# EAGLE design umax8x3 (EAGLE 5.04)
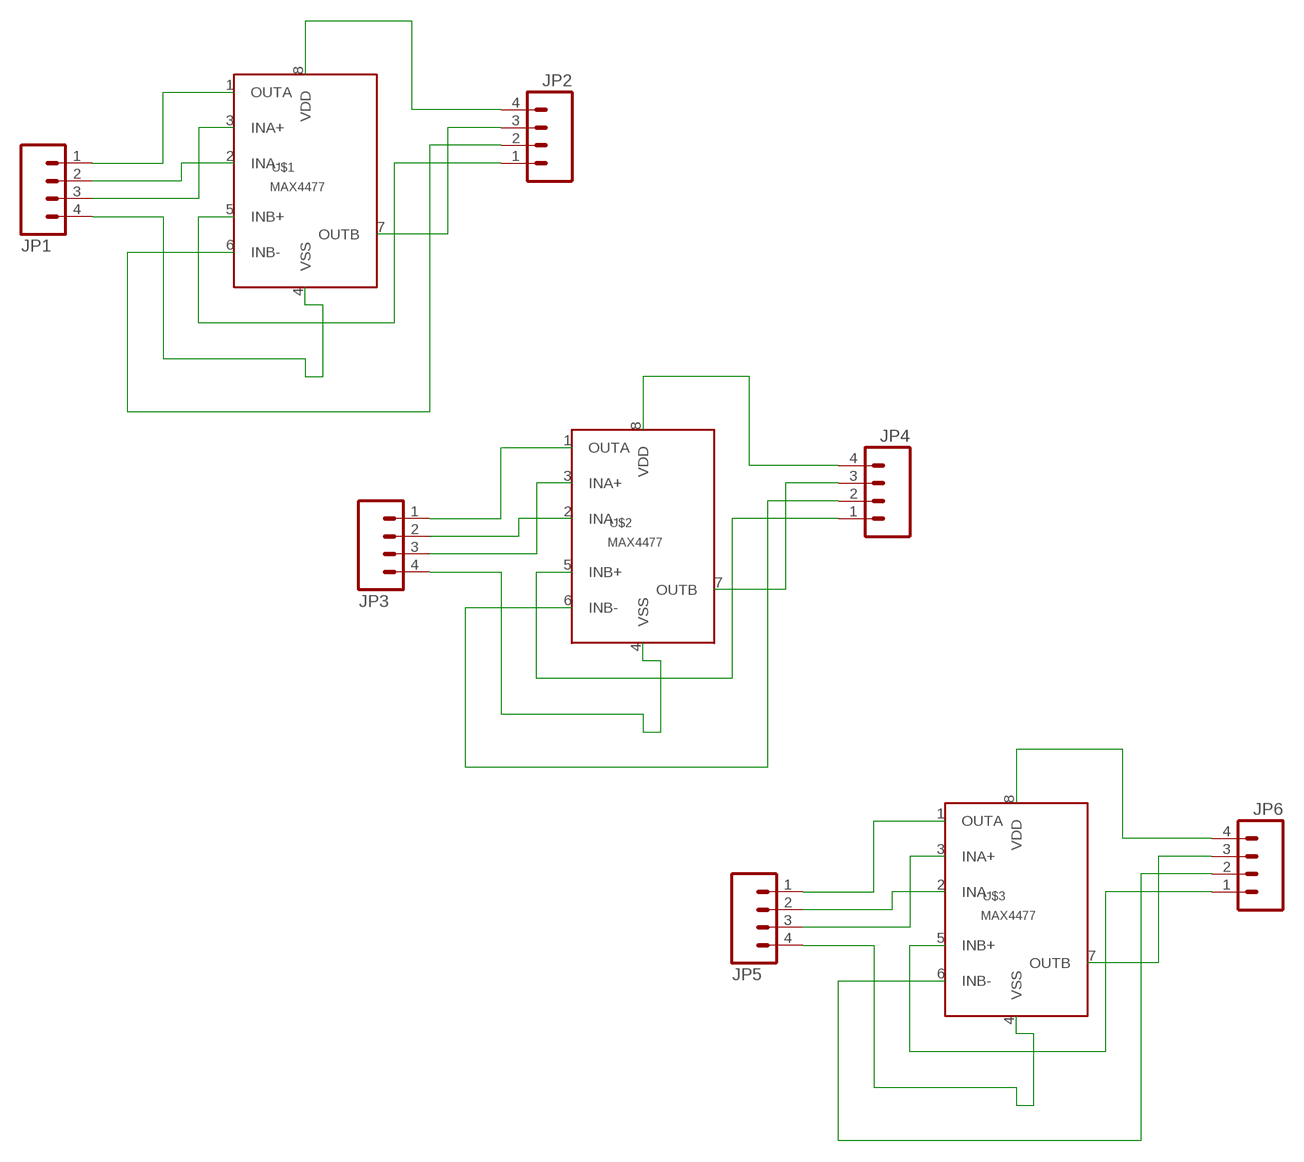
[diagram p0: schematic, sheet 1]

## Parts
JP1  M04PTH  [1X04]
JP2  M04PTH  [1X04]
JP3  M04PTH  [1X04]
JP4  M04PTH  [1X04]
JP5  M04PTH  [1X04]
JP6  M04PTH  [1X04]
U$1  MAX4477  [UMAX8]
U$2  MAX4477  [UMAX8]
U$3  MAX4477  [UMAX8]

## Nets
N$1: JP1.1 U$1.1(OUTA)
N$2: JP1.2 U$1.2(INA-)
N$3: JP1.3 U$1.3(INA+)
N$4: JP1.4 U$1.4(VSS)
N$5: JP2.1 U$1.5(INB+)
N$6: JP2.2 U$1.6(INB-)
N$7: JP2.3 U$1.7(OUTB)
N$8: JP2.4 U$1.8(VDD)
N$9: JP3.1 U$2.1(OUTA)
N$10: JP3.2 U$2.2(INA-)
N$11: JP3.3 U$2.3(INA+)
N$12: JP3.4 U$2.4(VSS)
N$13: JP4.1 U$2.5(INB+)
N$14: JP4.2 U$2.6(INB-)
N$15: JP4.3 U$2.7(OUTB)
N$16: JP4.4 U$2.8(VDD)
N$17: JP5.1 U$3.1(OUTA)
N$18: JP5.2 U$3.2(INA-)
N$19: JP5.3 U$3.3(INA+)
N$20: JP5.4 U$3.4(VSS)
N$21: JP6.1 U$3.5(INB+)
N$22: JP6.2 U$3.6(INB-)
N$23: JP6.3 U$3.7(OUTB)
N$24: JP6.4 U$3.8(VDD)

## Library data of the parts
JP1-JP6 = SparkFun:M04: Header 4 Standard 4-pin 0.1" header. Use with straight break away headers (SKU : PRT-00116), right angle break away headers (PRT-00553), swiss pins (PRT-00743), machine pins (PRT-00117), and female headers (PRT-00115). Molex polarized connector foot print use with SKU : PRT-08231 with associated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
U$1-U$3 = trl:MAX4477

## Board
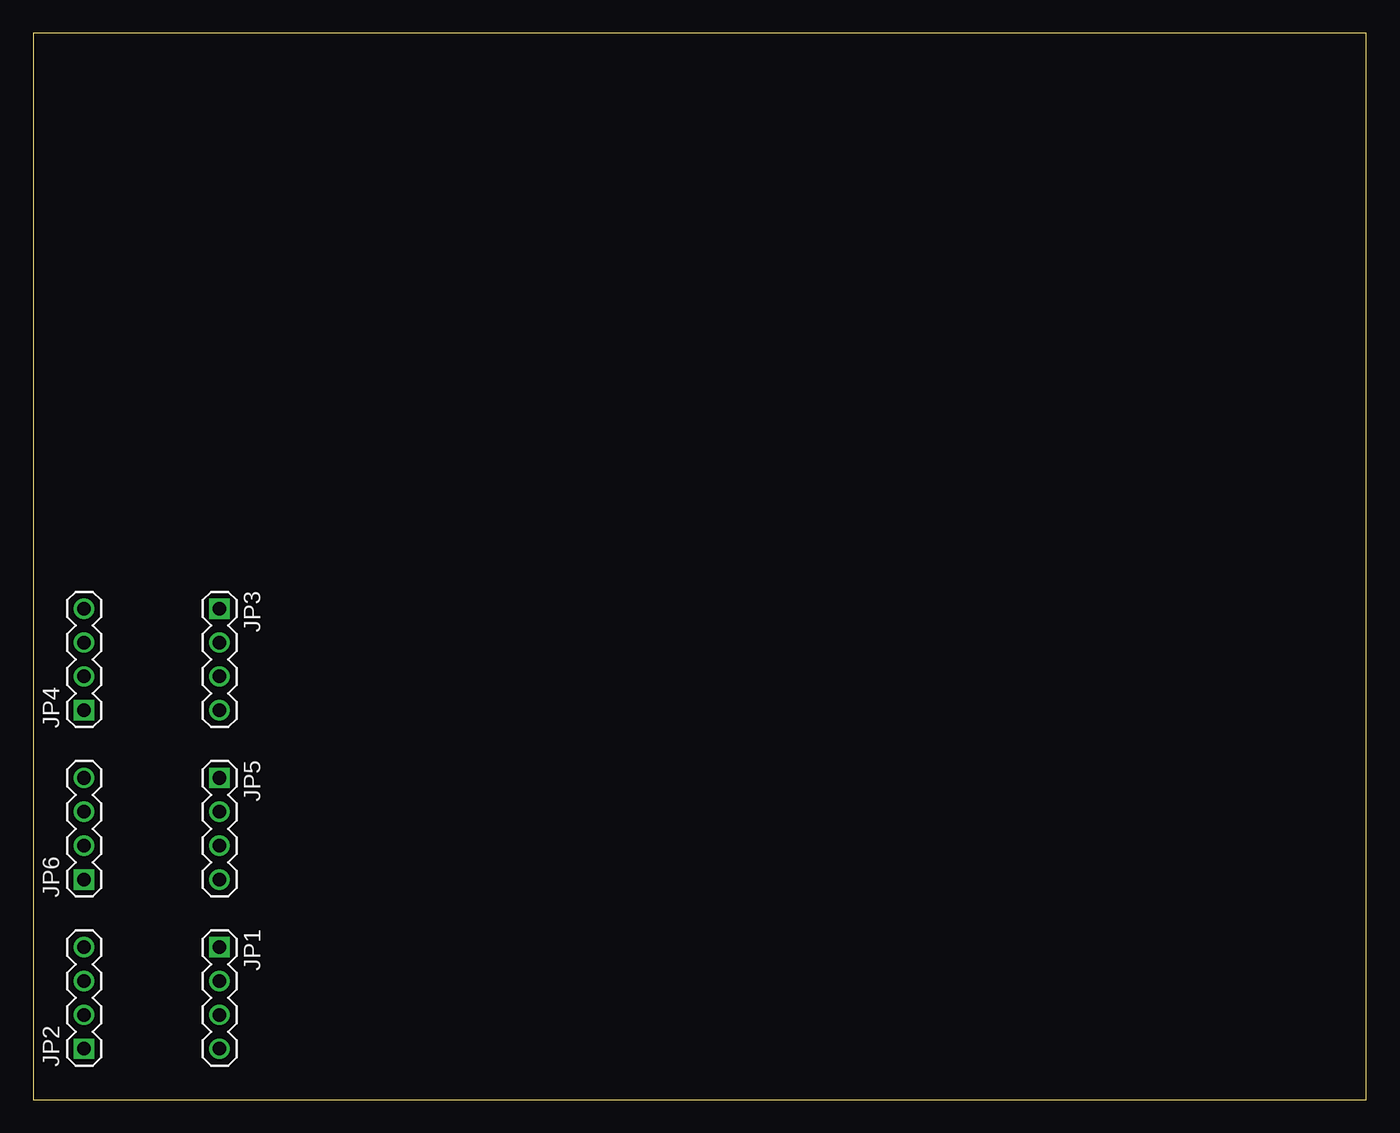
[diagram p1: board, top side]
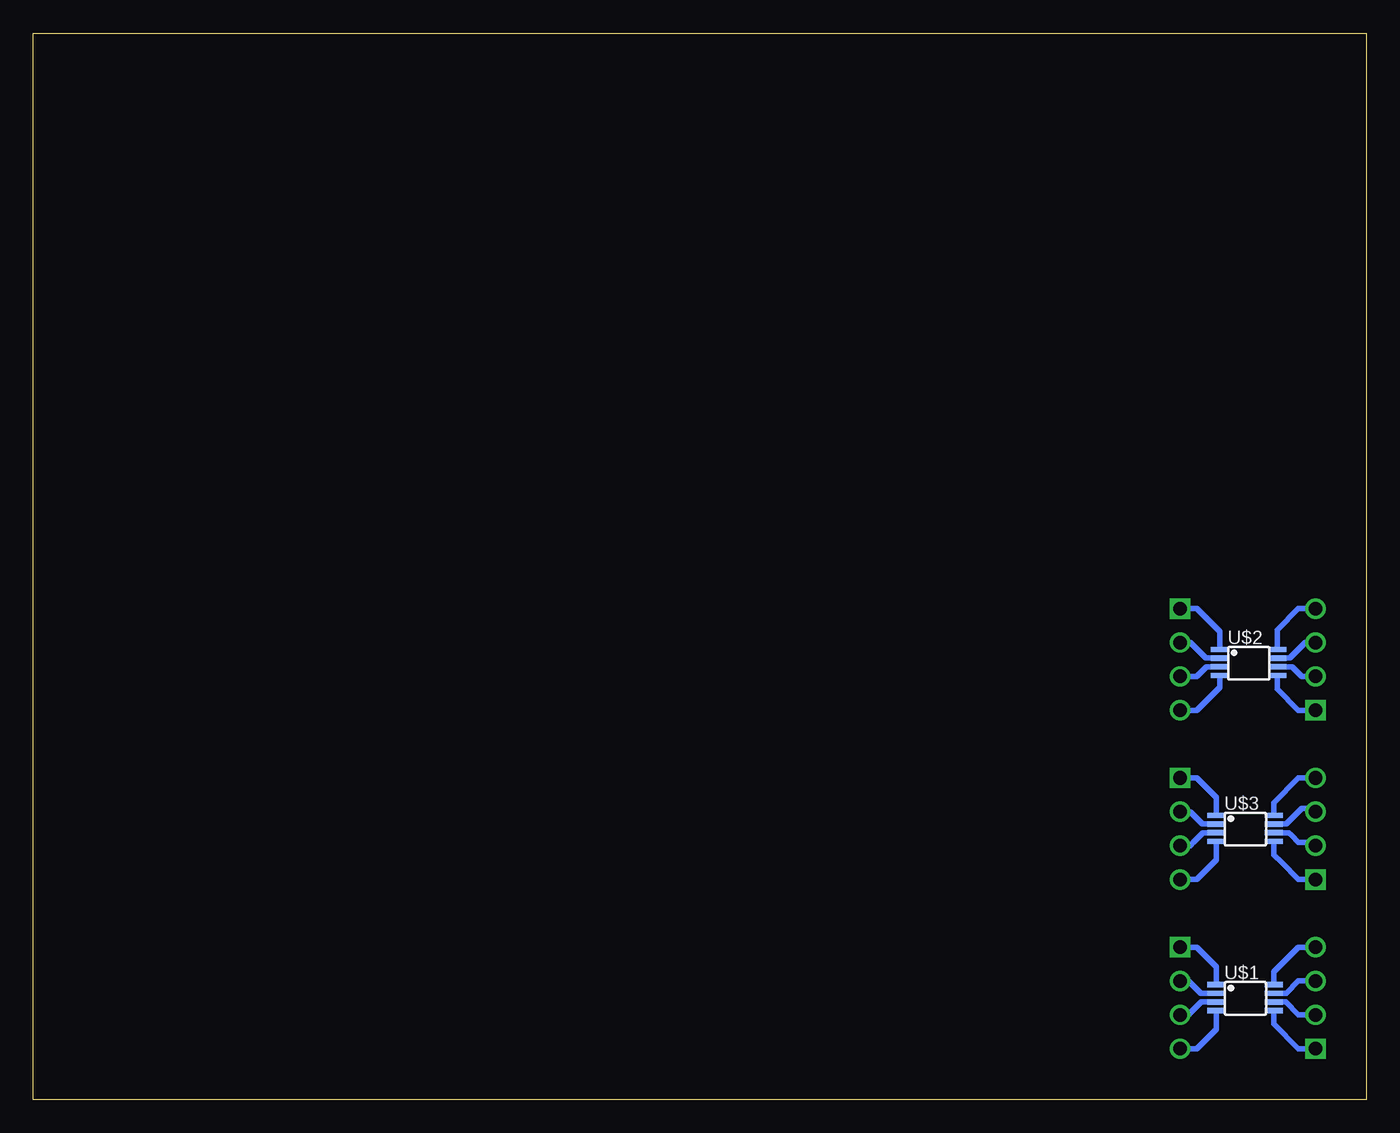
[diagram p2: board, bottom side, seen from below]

Size 100 x 80 mm. Coordinates in mm from the lower left corner, seen from the top.
Outline: 0,0 100,0 100,80 0,80 0,0
Copper layers (1*16): Top 0.035mm / dielectric 1.5mm / Bottom 0.035mm
Design rules "default": minimum track width 10mil, minimum drill 24mil, track to track 8mil, track to pad 8mil, pad to pad 8mil, via to via 8mil, smd to smd 8mil, copper to edge 40mil, drill to drill 8mil, minimum pad ring 10mil, minimum via ring 8mil, stop-mask expansion 4mil, vias tented up to drill 0mil, thermal gap 10mil

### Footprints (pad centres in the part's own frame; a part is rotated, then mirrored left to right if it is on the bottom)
1X04 = drill 1.016 square: 1 0,0 | drill 1.016 round: 2 2.54,0; 3 5.08,0; 4 7.62,0
UMAX8 = smd 1.35 x 0.4: 1 -2.35,1; 2 -2.35,0.35; 3 -2.35,-0.3; 4 -2.35,-0.95; 5 1.95,-0.95; 6 1.95,-0.3; 7 1.95,0.35; 8 1.95,1

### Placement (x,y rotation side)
JP1  13.97,11.43 270 top
JP2  3.81,3.81 90 top
JP3  13.97,36.83 270 top
JP4  3.81,29.21 90 top
JP5  13.97,24.13 270 top
JP6  3.81,16.51 90 top
U$1  8.89,7.62 0 bottom
U$2  8.64,32.77 0 bottom
U$3  8.89,20.32 0 bottom

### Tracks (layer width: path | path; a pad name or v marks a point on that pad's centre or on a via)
N$1
  Bottom 0.406: U$1.1 11.24,9.97 12.7,11.43 JP1.1
N$2
  Bottom 0.406: U$1.2 11.78,7.97 12.41,7.97 12.7,8.26 13.34,8.89 JP1.2
N$3
  Bottom 0.406: U$1.3 11.73,7.32 12.37,7.32 13.34,6.35 JP1.3
N$4
  Bottom 0.406: U$1.4 11.24,5.27 12.7,3.81 JP1.4
N$5
  Bottom 0.406: U$1.5 6.94,5.67 5.08,3.81 JP2.1
N$6
  Bottom 0.406: U$1.6 6.05,7.32 5.08,6.35 JP2.2
N$7
  Bottom 0.406: U$1.7 6,7.97 5.08,8.89 JP2.3
N$8
  Bottom 0.406: U$1.8 6.94,9.57 5.08,11.43 JP2.4
N$9
  Bottom 0.406: U$2.1 10.99,35.12 12.7,36.83 JP3.1
N$10
  Bottom 0.406: U$2.2 12.03,33.12 12.45,33.53 13.21,34.29 JP3.2
N$11
  Bottom 0.406: U$2.3 11.98,32.47 12.19,32.26 12.7,31.75 JP3.3
N$12
  Bottom 0.406: U$2.4 10.99,30.92 12.7,29.21 JP3.4
N$13
  Bottom 0.406: U$2.5 6.69,30.82 5.08,29.21 JP4.1
N$14
  Bottom 0.406: U$2.6 5.54,32.47 4.83,31.75 JP4.2
N$15
  Bottom 0.406: U$2.7 5.75,33.12 5.59,33.27 4.57,34.29 JP4.3
N$16
  Bottom 0.406: U$2.8 6.69,35.22 5.08,36.83 JP4.4
N$17
  Bottom 0.406: U$3.1 11.24,22.67 12.7,24.13 JP5.1
N$18
  Bottom 0.406: U$3.2 12.29,20.67 13.21,21.59 JP5.2
N$19
  Bottom 0.406: U$3.3 12.24,20.02 12.95,19.3 13.21,19.05 JP5.3
N$20
  Bottom 0.406: U$3.4 11.24,17.97 12.7,16.51 JP5.4
N$21
  Bottom 0.406: U$3.5 6.94,18.37 6.35,17.78 5.08,16.51 JP6.1
N$22
  Bottom 0.406: U$3.6 5.8,20.02 5.59,19.81 5.08,19.3 4.06,19.3 JP6.2
N$23
  Bottom 0.406: U$3.7 6,20.67 4.83,21.84 4.06,21.84 JP6.3
N$24
  Bottom 0.406: U$3.8 6.94,22.27 5.08,24.13 JP6.4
